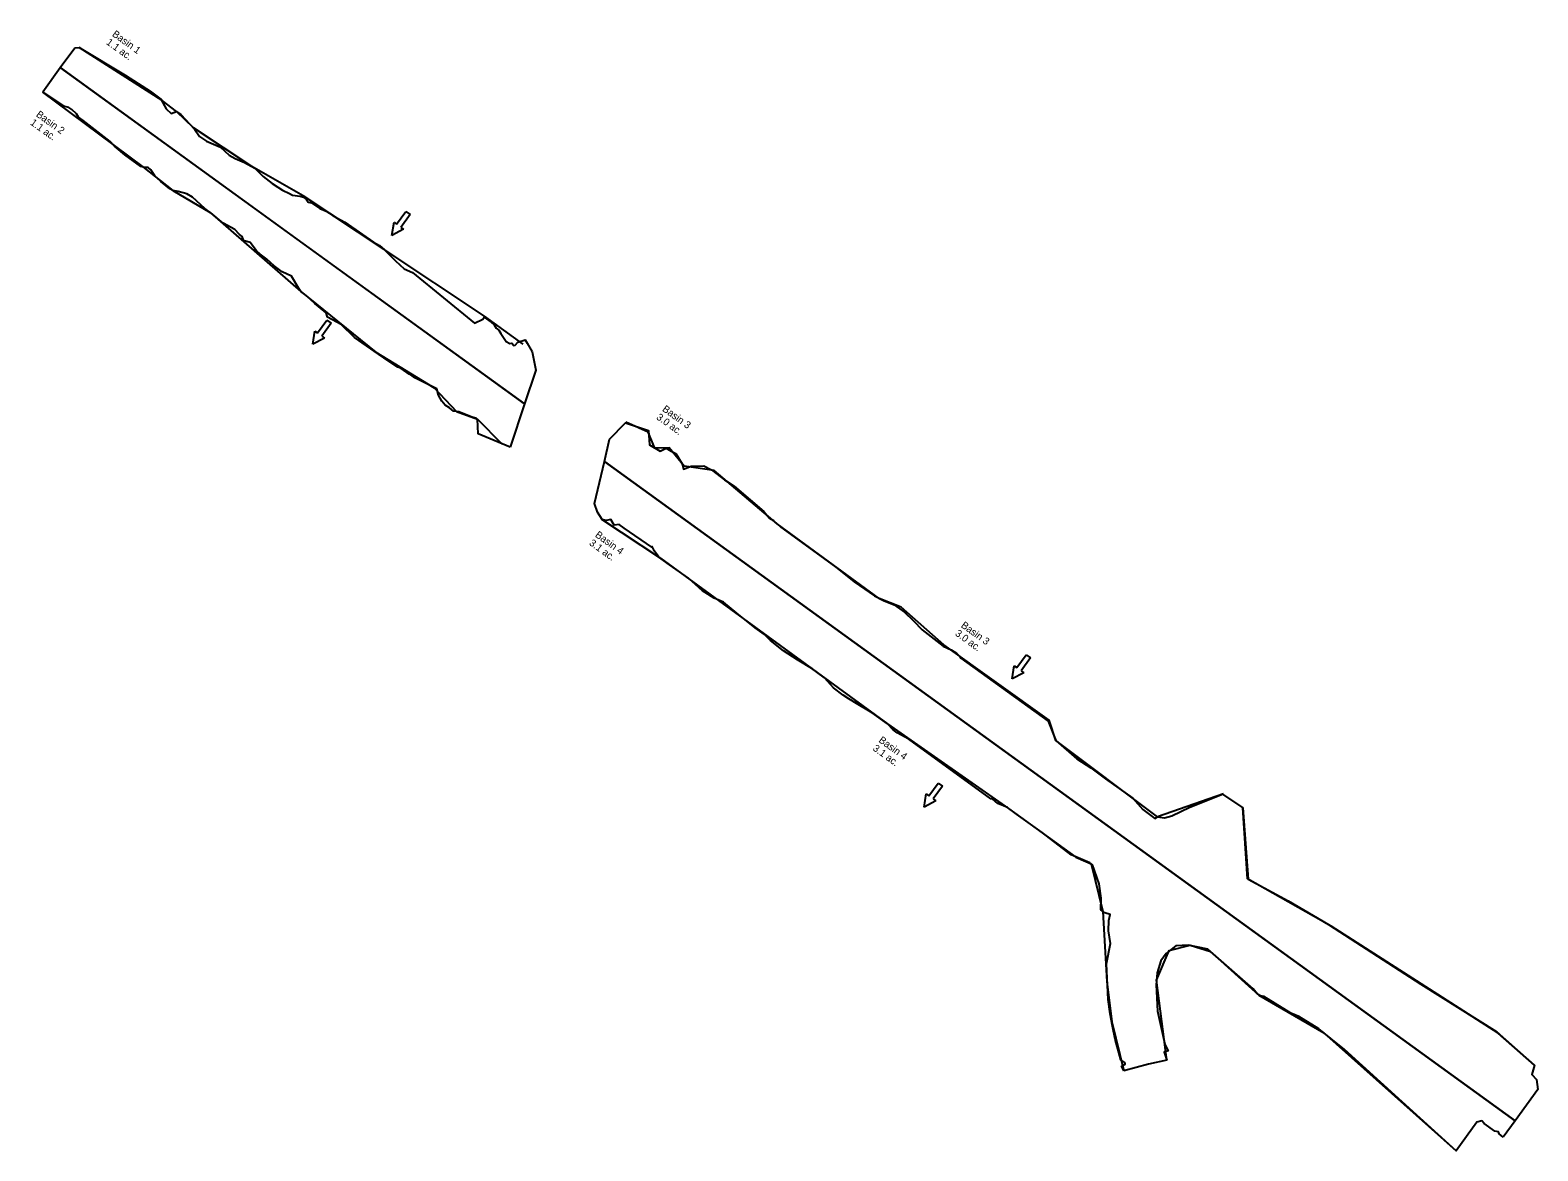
# Model space of a CAD drawing. Extents: x 14312393 to 14314661, y 8682290 to 8683975.
import ezdxf

# ---------------------------------------------------------------- set-up
doc = ezdxf.new("R2010")
doc.units = 0
for name, color, linetype in [('BasinText', 7, 'Continuous'), ('Contours Minor', 7, 'Continuous'), ('SheetText', 7, 'Continuous'), ('Terrain', 7, 'Continuous'), ('Text', 7, 'Continuous'), ('TextAlignment', 7, 'Continuous')]:
    doc.layers.add(name, color=color, linetype=linetype)

msp = doc.modelspace()

# ---------------------------------------------------------------- linework, layer by layer
at = {"layer": 'Contours Minor'}
for p, q in [((14312944.5, 8683683.1), (14312958.5, 8683702.4)), ((14312965, 8683697.8), (14312951, 8683678.4)), ((14312958.5, 8683702.4), (14312965, 8683697.8)), ((14312937.3, 8683666.3), (14312940.5, 8683686)), ((14312955, 8683675.5), (14312937.3, 8683666.3)), ((14312940.5, 8683686), (14312944.5, 8683683.1)), ((14312951, 8683678.4), (14312955, 8683675.5)), ((14312825.6, 8683519.6), (14312839.6, 8683538.9)), ((14312839.6, 8683538.9), (14312846.1, 8683534.3)), ((14312818.4, 8683502.8), (14312821.6, 8683522.5)), ((14312821.6, 8683522.5), (14312825.6, 8683519.6)), ((14312846.1, 8683534.3), (14312832.1, 8683514.9)), ((14312832.1, 8683514.9), (14312836.1, 8683512)), ((14312836.1, 8683512), (14312818.4, 8683502.8)), ((14313869.9, 8682999.5), (14313873.1, 8683019.2)), ((14313873.1, 8683019.2), (14313877.1, 8683016.3)), ((14313877.1, 8683016.3), (14313891.1, 8683035.6)), ((14313897.6, 8683031), (14313883.6, 8683011.7)), ((14313891.1, 8683035.6), (14313897.6, 8683031)), ((14313887.6, 8683008.7), (14313869.9, 8682999.5)), ((14313883.6, 8683011.7), (14313887.6, 8683008.7)), ((14313744.9, 8682823.5), (14313758.8, 8682842.8)), ((14313765.3, 8682838.2), (14313751.3, 8682818.8)), ((14313758.8, 8682842.8), (14313765.3, 8682838.2)), ((14313737.6, 8682806.7), (14313740.8, 8682826.4)), ((14313755.3, 8682815.9), (14313737.6, 8682806.7)), ((14313740.8, 8682826.4), (14313744.9, 8682823.5)), ((14313751.3, 8682818.8), (14313755.3, 8682815.9))]:
    msp.add_line(p, q, dxfattribs=at)
for points in [[(14313134.6, 8683502.9), (14313076.6, 8683544.9), (14312925.6, 8683644.9), (14312803.7, 8683725.6), (14312726.7, 8683770.1), (14312639, 8683828), (14312613.5, 8683852.5), (14312591.7, 8683869.3), (14312467.2, 8683948.8)], [(14312411.9, 8683881.7), (14312562.6, 8683769.4), (14312608, 8683734.1), (14312664.2, 8683700.9), (14312800.5, 8683582.1), (14312913.3, 8683490.7), (14313001.1, 8683437.2), (14313034.6, 8683401.3), (14313066, 8683390.2), (14313102.8, 8683353)], [(14314188.1, 8682826.6), (14314088.6, 8682791.9), (14313935.9, 8682906.8), (14313925.8, 8682937.1), (14313767.4, 8683050.5), (14313703.1, 8683107.1), (14313669.9, 8683120.4), (14313516.7, 8683232.7), (14313421.8, 8683312.8), (14313377, 8683319.4), (14313354.2, 8683347), (14313332.8, 8683346.6), (14313322.5, 8683370.3), (14313289.3, 8683385.5)], [(14313252.5, 8683239.8), (14313341.1, 8683180.7), (14313682.6, 8682931.7), (14313864.6, 8682804.6), (14313965.9, 8682731.5), (14313989.1, 8682721.5), (14314006.3, 8682649.8), (14314012.7, 8682544.4), (14314019.8, 8682483.5), (14314038.1, 8682410)], [(14314655.6, 8682418.5), (14314601, 8682466.7), (14314349.9, 8682627.3), (14314224.1, 8682698.6), (14314217.2, 8682805.5)], [(14314102.9, 8682426.2), (14314086.9, 8682546.5), (14314106.4, 8682591), (14314138, 8682598.9), (14314168.3, 8682589.6), (14314241.2, 8682524), (14314339, 8682467.2), (14314537.6, 8682289.6)]]:
    msp.add_lwpolyline(points, dxfattribs=at)
at = {"layer": 'SheetText'}
for p, q in [((14313242.1, 8683263.4), (14313256.9, 8683326.3)), ((14313256.9, 8683326.3), (14314119.7, 8682701.5)), ((14314119.7, 8682701.5), (14314119.7, 8682701.6)), ((14314119.7, 8682701.6), (14314626.4, 8682334.7)), ((14314102.9, 8682426.2), (14314075, 8682419.8)), ((14314075, 8682419.8), (14314038.1, 8682410)), ((14314626.4, 8682334.7), (14314608.6, 8682310.1))]:
    msp.add_line(p, q, dxfattribs=at)
for points in [[(14314038.1, 8682410), (14314034.5, 8682417), (14314039.8, 8682419.8), (14314039.7, 8682422.5), (14314033.6, 8682426.3), (14314025, 8682457.6), (14314021.2, 8682477.3), (14314017.4, 8682495.8), (14314014.6, 8682517.3), (14314011.9, 8682570.8), (14314018.2, 8682601.4), (14314015.2, 8682620.5), (14314015.3, 8682635.9), (14314017.3, 8682645.3), (14314009.7, 8682647.6), (14314003.6, 8682652), (14314004.1, 8682669.7), (14314001.1, 8682691.2), (14313991.1, 8682720), (14313987.1, 8682722.9), (14313958.6, 8682734.8), (14313915.1, 8682768.5), (14313876.5, 8682796.2), (14313863, 8682806), (14313848.3, 8682812.2), (14313840.4, 8682818.8), (14313837.8, 8682819.2), (14313714.5, 8682908.5), (14313708, 8682912.5), (14313697.1, 8682918.2), (14313691.1, 8682922.6), (14313682.6, 8682931.7), (14313659.5, 8682948.3), (14313635.9, 8682962.6), (14313624.7, 8682969.6), (14313615.9, 8682974.8), (14313601.3, 8682985.9), (14313588, 8683001.1), (14313568.8, 8683014.9), (14313547.4, 8683027.9), (14313526.4, 8683041.6), (14313506.7, 8683057), (14313497.7, 8683065.9), (14313483.6, 8683076.2), (14313456.2, 8683098), (14313436.1, 8683114.9), (14313422, 8683120.9), (14313404.5, 8683131.8), (14313383.4, 8683150.9), (14313354.7, 8683171), (14313342.5, 8683179.7), (14313338.2, 8683183.3), (14313332, 8683191.5), (14313328.7, 8683198.3), (14313328.2, 8683197.7), (14313286.5, 8683226.1), (14313279.3, 8683231.6), (14313271.4, 8683230.8), (14313266.4, 8683239.1), (14313259.8, 8683237.7), (14313253.4, 8683239.1), (14313246.5, 8683250.3), (14313242.1, 8683263.4)], [(14314608.6, 8682310.1), (14314602.5, 8682315.4), (14314601.4, 8682318.2), (14314595.9, 8682319), (14314579.7, 8682330.8), (14314576.3, 8682334.6), (14314568.7, 8682332.6), (14314537.6, 8682289.6), (14314370.1, 8682441.9), (14314331.1, 8682473.3), (14314301, 8682491.5), (14314289.4, 8682496.8), (14314248.6, 8682521.5), (14314243.4, 8682522.8), (14314239, 8682525.3), (14314232.6, 8682533.4), (14314164.5, 8682592.9), (14314135.1, 8682599.1), (14314116.3, 8682598.1), (14314101.8, 8682586.4), (14314093.5, 8682575.6), (14314088.2, 8682557.1), (14314086.5, 8682539.3), (14314088.5, 8682499.7), (14314099.6, 8682450.2), (14314104.6, 8682440.1), (14314098.9, 8682437.9), (14314102.9, 8682426.2)]]:
    msp.add_lwpolyline(points, dxfattribs=at)
at = {"layer": 'Terrain'}
for p, q in [((14312412.3, 8683882.1), (14312438.7, 8683918.6)), ((14312438.7, 8683918.6), (14312803.6, 8683654.4)), ((14312803.6, 8683654.4), (14313136.9, 8683413.1)), ((14313136.9, 8683413.1), (14313115, 8683347.8))]:
    msp.add_line(p, q, dxfattribs=at)
for points in [[(14312772.3, 8683611.4), (14312760.3, 8683620.4), (14312749.2, 8683630.7), (14312739.2, 8683638.2), (14312733.5, 8683643), (14312724.1, 8683655.6), (14312715.5, 8683658.2), (14312714.4, 8683659.3), (14312712.1, 8683664.7), (14312708.2, 8683667.9), (14312701.3, 8683675.3), (14312683.4, 8683684.8), (14312668.1, 8683697.7), (14312656.2, 8683706.8), (14312637.6, 8683723.8), (14312628.8, 8683728.6), (14312615.9, 8683732.2), (14312608, 8683734.1), (14312603.6, 8683736.5), (14312597.7, 8683741.1), (14312589.9, 8683747.5), (14312584.1, 8683752.2), (14312580.7, 8683756), (14312574.6, 8683764.7), (14312571, 8683768.2), (14312565.2, 8683768.7), (14312560, 8683770.1), (14312535.5, 8683787.3), (14312520.3, 8683800.5), (14312513.8, 8683807.5), (14312473.1, 8683839), (14312465.9, 8683844.2), (14312462.9, 8683849), (14312456, 8683855.7), (14312451.4, 8683858.8), (14312445.7, 8683860.2), (14312412.3, 8683882.1)], [(14313115, 8683347.8), (14313067.2, 8683368.1), (14313066, 8683390.2), (14313064.6, 8683391.1), (14313056.6, 8683393.6), (14313038.2, 8683400.9), (14313030, 8683402.2), (14313023.8, 8683407), (14313017.6, 8683410.9), (14313012.2, 8683416.9), (14313007.5, 8683426.2), (14313004.7, 8683435.6), (14312971.8, 8683452.1), (14312967.7, 8683455), (14312963.5, 8683457.7), (14312951.2, 8683466.3), (14312946.5, 8683468.4), (14312931.6, 8683477.6), (14312917.4, 8683487.8), (14312881.2, 8683512.6), (14312861.1, 8683532.5), (14312840.7, 8683543.4), (14312838.7, 8683549.7), (14312821.3, 8683564), (14312808.3, 8683575.8), (14312800.5, 8683582.1), (14312797.4, 8683586.3), (14312786.3, 8683605.2), (14312772.3, 8683611.4)]]:
    msp.add_lwpolyline(points, dxfattribs=at)
at = {"layer": 'Text'}
for p, q in [((14312438.7, 8683918.6), (14312460.3, 8683948.4)), ((14313136.9, 8683413.1), (14312438.7, 8683918.6)), ((14313153.9, 8683463.8), (14313136.9, 8683413.1))]:
    msp.add_line(p, q, dxfattribs=at)
for points in [[(14312460.3, 8683948.4), (14312467.2, 8683948.8), (14312536.1, 8683907.5), (14312573.9, 8683883.1), (14312590, 8683871.2), (14312598.1, 8683856.8), (14312605.4, 8683849.8), (14312613.5, 8683852.5), (14312619.7, 8683848.2), (14312640.6, 8683826), (14312648.2, 8683815.2), (14312658.6, 8683808.1), (14312679.6, 8683798.8), (14312692.7, 8683787.1), (14312701.5, 8683782.1), (14312715.7, 8683776.2), (14312731, 8683767.5), (14312743.5, 8683755), (14312757.4, 8683744.2), (14312765.9, 8683739), (14312772.6, 8683734.2), (14312783.6, 8683729.4), (14312787.8, 8683726.7), (14312799.2, 8683725.3), (14312804.3, 8683723.7), (14312808.5, 8683721), (14312811.2, 8683716.2), (14312816.5, 8683715.1), (14312829, 8683706.7), (14312838.4, 8683702.6)], [(14312838.4, 8683702.6), (14312848.9, 8683695.8), (14312866.5, 8683686.2), (14312909.7, 8683656.2), (14312918.6, 8683650.9), (14312925.6, 8683644.9), (14312943, 8683628.2), (14312955.8, 8683616), (14312968.2, 8683610.4), (14313061.6, 8683534.2), (14313074.3, 8683540.2), (14313076, 8683543.2), (14313086.4, 8683535.8), (14313091.2, 8683532), (14313094, 8683526.8), (14313097.9, 8683523.6), (14313101.4, 8683518.7), (14313109.4, 8683506.6), (14313114.8, 8683503.7), (14313117.7, 8683504.5), (14313120.6, 8683501), (14313122.5, 8683501.3), (14313126.6, 8683505.6), (14313137.7, 8683509.5), (14313140.8, 8683504.3), (14313148.4, 8683491), (14313153.9, 8683463.8)]]:
    msp.add_lwpolyline(points, dxfattribs=at)
at = {"layer": 'TextAlignment'}
for p, q in [((14313256.9, 8683326.3), (14313264.8, 8683360.1)), ((14314081.6, 8682729.2), (14313256.9, 8683326.3)), ((14314626.4, 8682334.7), (14314081.6, 8682729.2)), ((14314660.6, 8682381.9), (14314626.4, 8682334.7))]:
    msp.add_line(p, q, dxfattribs=at)
for points in [[(14313264.8, 8683360.1), (14313288.6, 8683384.7), (14313323, 8683373.1), (14313324.7, 8683351.4), (14313340.7, 8683342), (14313349.7, 8683346.3), (14313357.1, 8683342.1), (14313364.2, 8683338.3), (14313373.7, 8683322.9), (14313375.6, 8683314.7), (14313387.3, 8683319.4), (14313406.5, 8683319.7), (14313418, 8683313.6), (14313437.7, 8683298.5), (14313452, 8683289.4), (14313496.8, 8683251.3), (14313505.4, 8683241.3), (14313511.1, 8683237.8), (14313522.2, 8683227.4), (14313605.1, 8683167.4), (14313632.5, 8683145.4), (14313663.3, 8683124.1), (14313676.8, 8683117.1), (14313692.7, 8683110.7), (14313708.4, 8683099.9), (14313721.9, 8683086.9), (14313735, 8683073.1), (14313766.4, 8683048.8), (14313778.2, 8683043.2), (14313786.2, 8683037.9), (14313791.6, 8683033.1), (14313793, 8683030.7), (14313924.1, 8682935.7), (14313935.9, 8682906.8), (14313967.2, 8682879.3), (14313988.5, 8682865.7), (14314010.5, 8682849), (14314051.8, 8682819.8), (14314066.8, 8682803), (14314084.7, 8682789.6), (14314088.6, 8682791.9), (14314099.1, 8682790.6), (14314110.2, 8682793.6), (14314137.4, 8682806.3)], [(14314137.4, 8682806.3), (14314186.3, 8682826.1), (14314217.2, 8682805.5), (14314225.1, 8682698), (14314284.9, 8682665.4), (14314345.7, 8682630), (14314484.5, 8682540.3), (14314599.1, 8682468.4), (14314655.6, 8682418.5), (14314651.6, 8682404.4), (14314658.5, 8682397), (14314660.6, 8682381.9)]]:
    msp.add_lwpolyline(points, dxfattribs=at)

# ---------------------------------------------------------------- texts
at = {"layer": 'BasinText'}
for s, p in [('Basin 1', (14312515.7, 8683966.9)), ('1.1 ac.', (14312506.8, 8683954.7)), ('Basin 2', (14312401.3, 8683846.1)), ('1.1 ac.', (14312392.5, 8683833.8)), ('Basin 3', (14313343, 8683403.1)), ('3.0 ac.', (14313334.1, 8683390.9)), ('Basin 4', (14313242, 8683213.9)), ('3.1 ac.', (14313233.1, 8683201.7)), ('Basin 3', (14313792.2, 8683077.9)), ('3.0 ac.', (14313783.3, 8683065.7)), ('Basin 4', (14313668.4, 8682905.2)), ('3.1 ac.', (14313659.5, 8682892.9))]:
    msp.add_text(s, height=10.8, rotation=324.094, dxfattribs=at).set_placement(p)

doc.saveas('drawing.dxf')
